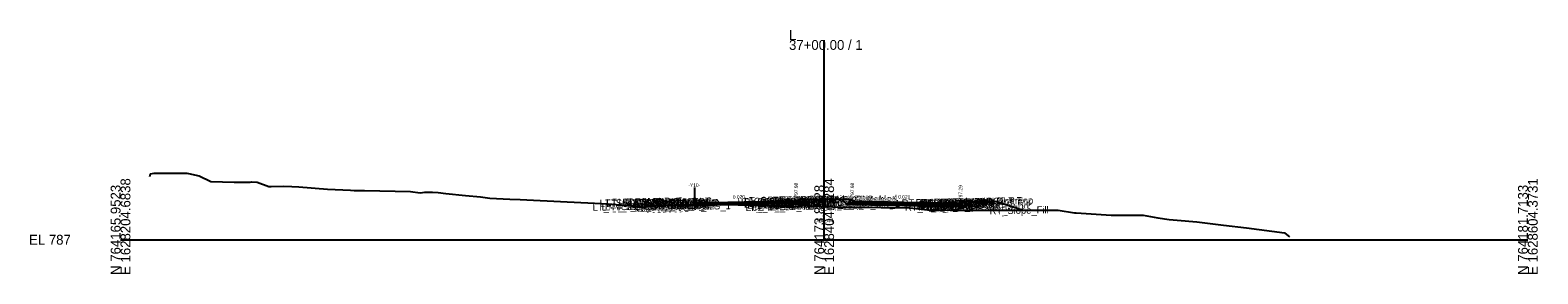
# Model space of a CAD drawing. Extents: x -26 to 4403, y -510 to 9556.
# Drawn here: x 1974.3 to 2402.8, y 6990.3 to 7059.6 of the extents above; entities that cross this region are included whole.
import ezdxf

# ---------------------------------------------------------------- set-up
doc = ezdxf.new("R2010")
doc.units = 0
for name, color, linetype in [('Default', 7, 'Continuous'), ('Exist CMT Pavement', 7, 'Continuous'), ('Exist Cross Section Cell', 7, 'Continuous'), ('Exist XS Center Line Elevation Label', 7, 'Continuous'), ('Exist XS Ground Line', 7, 'Continuous'), ('Prop CMT Conc Surface', 7, 'Continuous'), ('Prop CMT Concrete Structures', 7, 'Continuous'), ('Prop CMT Pvmt Course 1', 7, 'Continuous'), ('Prop CMT Pvmt Course 1 CG', 7, 'Continuous'), ('Prop CMT Pvmt Course 2', 7, 'Continuous'), ('Prop CMT Pvmt Course 2 Wedge', 7, 'Continuous'), ('Prop CMT Pvmt Course 3', 7, 'Continuous'), ('Prop CMT Pvmt Course 3 Wedge', 7, 'Continuous'), ('Prop CMT Pvmt Surface', 7, 'Continuous'), ('Prop CMT Shear Line', 7, 'Continuous'), ('Prop CMT Slope Grass', 7, 'Continuous'), ('Prop CMT Subgrade Earthwork', 7, 'Continuous'), ('Prop XS Hydro Elevations', 7, 'Continuous'), ('Prop XS SE Text', 7, 'Continuous'), ('Prop XS Side Slope Text', 7, 'Continuous'), ('Scratch_Level_0', 7, 'Continuous')]:
    doc.layers.add(name, color=color, linetype=linetype)

msp = doc.modelspace()

# ---------------------------------------------------------------- linework, layer by layer
at = {"layer": 'Exist CMT Pavement'}
for points in [[(2149.21, 7009.52), (2149.21, 7009.52)], [(2163.25, 7009.95), (2169.01, 7009.97), (2172.14, 7009.98), (2178.99, 7009.83), (2181.8, 7009.77), (2184.46, 7009.67), (2191.07, 7009.43)]]:
    msp.add_lwpolyline(points, dxfattribs=at)
at = {"layer": 'Exist Cross Section Cell'}
for p, q in [((2200, 7000), (2200, 7056.77)), ((2000, 7000), (2200, 7000)), ((2200, 7000), (2400, 7000))]:
    msp.add_line(p, q, dxfattribs=at)
at = {"layer": 'Exist XS Ground Line'}
msp.add_lwpolyline([(2008.31, 7017.94), (2008.54, 7018.7), (2009.52, 7018.92), (2018.01, 7018.92), (2018.86, 7018.91), (2019.34, 7018.83), (2022.31, 7018.12), (2025.65, 7016.51), (2032.34, 7016.34), (2036.84, 7016.37), (2037.31, 7016.49), (2038.86, 7016.36), (2042.15, 7015.14), (2042.83, 7015.17), (2046.28, 7015.22), (2048.72, 7015.1), (2050.63, 7015.02), (2058.81, 7014.34), (2065.32, 7014.05), (2066.36, 7013.97), (2069.31, 7013.99), (2082.42, 7013.68), (2085.13, 7013.38), (2086.47, 7013.57), (2088.62, 7013.52), (2090.31, 7013.45), (2092.41, 7013.18), (2098.08, 7012.57), (2102.31, 7012.2), (2105, 7011.85), (2110.65, 7011.58), (2113.57, 7011.47), (2126.99, 7010.79), (2136.72, 7010.27), (2142.3, 7009.89), (2143.35, 7009.87), (2145.26, 7009.77), (2146.89, 7009.54), (2148.79, 7009.29), (2149.21, 7009.52), (2157.72, 7009.8), (2161.95, 7009.94), (2169.01, 7009.97), (2172.14, 7009.98), (2178.99, 7009.83), (2181.8, 7009.77), (2184.46, 7009.67), (2191.07, 7009.43), (2192.27, 7009.33), (2194.26, 7009.69), (2195.18, 7009.65), (2196.21, 7009.57), (2196.73, 7009.55), (2200, 7009.44), (2204.69, 7009.28), (2207.03, 7009.29), (2207.93, 7009.28), (2224.4, 7009.09), (2227.6, 7008.72), (2229.34, 7008.47), (2235.8, 7008.39), (2239.47, 7008.39), (2240.18, 7008.39), (2240.57, 7008.39), (2262.9, 7008.39), (2266.5, 7008.37), (2271.16, 7007.61), (2271.57, 7007.61), (2281.58, 7006.96), (2282.47, 7006.94), (2284.59, 7006.94), (2290.67, 7007), (2294.83, 7006.27), (2298.06, 7005.77), (2300.35, 7005.52), (2305.96, 7005.12), (2313.49, 7004.12), (2320.03, 7003.38), (2330.8, 7001.94), (2331.89, 7001.14), (2332.29, 7000.82)], dxfattribs=at)
at = {"layer": 'Prop CMT Conc Surface'}
for points in [[(2191.25, 7010.97), (2192, 7010.98), (2192, 7011.15), (2192.76, 7011.4)], [(2208.75, 7010.97), (2208, 7010.98), (2208, 7011.15), (2207.24, 7011.4)], [(2243.25, 7010.88), (2248.25, 7010.98)], [(2236.75, 7010.41), (2238.75, 7010.29)], [(2238.75, 7010.29), (2238.75, 7010.79), (2239.25, 7010.79)]]:
    msp.add_lwpolyline(points, dxfattribs=at)
at = {"layer": 'Prop CMT Concrete Structures'}
for points in [[(2191.25, 7010.97), (2192, 7010.98), (2192, 7011.15), (2192.76, 7011.4)], [(2191.25, 7010.39), (2191.25, 7010.97)], [(2192.76, 7011.4), (2192.76, 7010.42)], [(2208.75, 7010.97), (2208, 7010.98), (2208, 7011.15), (2207.24, 7011.4)], [(2207.24, 7011.4), (2207.24, 7010.42)], [(2208.75, 7010.39), (2208.75, 7010.97)], [(2248.25, 7010.98), (2243.25, 7010.88)], [(2243.25, 7010.88), (2243.25, 7010.55)], [(2248.25, 7010.65), (2248.25, 7010.98)], [(2192.76, 7010.42), (2191.25, 7010.39)], [(2207.24, 7010.42), (2208.75, 7010.39)], [(2236.75, 7010.41), (2238.75, 7010.29), (2238.75, 7010.79), (2239.25, 7010.79)], [(2239.25, 7010.79), (2239.25, 7009.78), (2236.75, 7009.83)], [(2236.75, 7009.83), (2236.75, 7010.41)], [(2243.25, 7010.55), (2248.25, 7010.65)]]:
    msp.add_lwpolyline(points, dxfattribs=at)
at = {"layer": 'Prop CMT Pvmt Course 1'}
for points in [[(2191.25, 7010.97), (2163.25, 7010.41)], [(2191.25, 7010.72), (2191.25, 7010.97)], [(2208.75, 7010.97), (2236.75, 7010.41)], [(2208.75, 7010.72), (2208.75, 7010.97)], [(2163.25, 7010.16), (2191.07, 7010.72), (2191.25, 7010.72)], [(2236.75, 7010.16), (2208.75, 7010.72)], [(2208.75, 7010.72), (2208.75, 7010.72), (2208.75, 7010.72)], [(2236.75, 7010.41), (2236.75, 7010.16)]]:
    msp.add_lwpolyline(points, dxfattribs=at)
at = {"layer": 'Prop CMT Pvmt Course 1 CG'}
for points in [[(2191.25, 7010.39), (2193.26, 7010.43), (2193.59, 7010.1)], [(2191.25, 7010.05), (2191.25, 7010.39)], [(2193.59, 7010.1), (2191.25, 7010.05)], [(2208.75, 7010.39), (2206.74, 7010.43), (2206.41, 7010.1)], [(2206.41, 7010.1), (2208.75, 7010.05)], [(2208.75, 7010.05), (2208.75, 7010.39)], [(2236.75, 7009.83), (2239.75, 7009.77), (2240.09, 7009.43)], [(2236.75, 7009.49), (2236.75, 7009.83)], [(2240.09, 7009.43), (2236.75, 7009.49)]]:
    msp.add_lwpolyline(points, dxfattribs=at)
at = {"layer": 'Prop CMT Pvmt Course 2'}
for points in [[(2191.07, 7010.72), (2191.07, 7010.38)], [(2191.25, 7010.72), (2191.07, 7010.72)], [(2191.07, 7010.38), (2191.25, 7010.39)], [(2191.25, 7010.39), (2191.25, 7010.72)], [(2208.75, 7010.39), (2208.75, 7010.72)], [(2208.75, 7010.72), (2236.75, 7010.16)], [(2236.75, 7009.83), (2208.75, 7010.39)], [(2236.75, 7010.16), (2236.75, 7009.83)]]:
    msp.add_lwpolyline(points, dxfattribs=at)
at = {"layer": 'Prop CMT Pvmt Course 2 Wedge'}
for points in [[(2191.07, 7010.38), (2191.07, 7010.38), (2184.46, 7010.25), (2181.8, 7010.2), (2178.99, 7010.14), (2172.14, 7010), (2170.63, 7009.97), (2169.01, 7009.97), (2161.95, 7009.94), (2160.34, 7009.89)], [(2163.25, 7010.16), (2169.01, 7010.27), (2172.14, 7010.34), (2178.99, 7010.47), (2181.8, 7010.53), (2184.46, 7010.58), (2191.07, 7010.72), (2191.07, 7010.72)], [(2191.07, 7010.72), (2191.07, 7010.38)]]:
    msp.add_lwpolyline(points, dxfattribs=at)
at = {"layer": 'Prop CMT Pvmt Course 3'}
for points in [[(2191.25, 7010.39), (2191.07, 7010.38)], [(2191.07, 7010.38), (2191.07, 7010.05)], [(2191.07, 7010.05), (2191.25, 7010.05)], [(2191.25, 7010.05), (2191.25, 7010.39)], [(2208.75, 7010.39), (2236.75, 7009.83)], [(2208.75, 7010.05), (2208.75, 7010.39)], [(2236.75, 7009.49), (2208.75, 7010.05)], [(2236.75, 7009.83), (2236.75, 7009.49)]]:
    msp.add_lwpolyline(points, dxfattribs=at)
at = {"layer": 'Prop CMT Pvmt Course 3 Wedge'}
for points in [[(2170.63, 7009.97), (2172.14, 7010)], [(2191.07, 7009.43), (2191.07, 7009.43), (2184.46, 7009.67), (2181.8, 7009.77), (2178.99, 7009.83), (2172.14, 7009.98), (2170.63, 7009.97)], [(2172.14, 7010), (2178.99, 7010.14), (2181.8, 7010.2), (2184.46, 7010.25), (2191.07, 7010.38), (2191.07, 7010.38)], [(2191.07, 7010.38), (2191.07, 7009.43)]]:
    msp.add_lwpolyline(points, dxfattribs=at)
at = {"layer": 'Prop CMT Pvmt Surface'}
for points in [[(2191.25, 7010.97), (2163.25, 7010.41)], [(2208.75, 7010.97), (2236.75, 7010.41)]]:
    msp.add_lwpolyline(points, dxfattribs=at)
at = {"layer": 'Prop CMT Shear Line'}
msp.add_line((2163.25, 7008.58), (2163.25, 7014.84), dxfattribs=at)
at = {"layer": 'Prop CMT Slope Grass'}
for points in [[(2192.76, 7011.4), (2200, 7011.55)], [(2207.24, 7011.4), (2200, 7011.55)], [(2239.25, 7010.79), (2248.75, 7010.98), (2256.53, 7008.39)]]:
    msp.add_lwpolyline(points, dxfattribs=at)
at = {"layer": 'Prop CMT Subgrade Earthwork'}
for points in [[(2194.93, 7011.44), (2193.59, 7010.1)], [(2205.07, 7011.44), (2206.41, 7010.1)], [(2236.75, 7009.49), (2240.09, 7009.43), (2241.5, 7010.83)], [(2191.25, 7010.05), (2191.07, 7010.05)], [(2191.07, 7010.05), (2191.07, 7009.43)], [(2193.59, 7010.1), (2191.25, 7010.05)], [(2191.25, 7010.05), (2191.25, 7010.05)], [(2206.41, 7010.1), (2208.75, 7010.05)], [(2208.75, 7010.05), (2236.75, 7009.49)], [(2208.75, 7010.05), (2208.75, 7010.05)], [(2208.75, 7010.05), (2208.75, 7010.05)], [(2236.75, 7009.49), (2236.75, 7009.49)]]:
    msp.add_lwpolyline(points, dxfattribs=at)

# ---------------------------------------------------------------- texts
at = {"layer": 'Default'}
msp.add_text('-', height=0.0001, dxfattribs=at).set_placement((2000, 7000))
at = {"layer": 'Exist Cross Section Cell'}
for s, p in [('L', (2190, 7056.77)), ('37+00.00 / 1', (2190, 7053.97)), ('EL 787', (1974, 6998.6))]:
    msp.add_text(s, height=2.8, dxfattribs=at).set_placement(p)
for s, p in [('N 764165.9523', (2000, 6990)), ('E 1628204.6838', (2002.8, 6990)), ('N 764173.8328', (2200, 6990)), ('E 1628404.5284', (2202.8, 6990)), ('N 764181.7133', (2400, 6990)), ('E 1628604.3731', (2402.8, 6990))]:
    msp.add_text(s, height=2.8, rotation=90, dxfattribs=at).set_placement(p)
at = {"layer": 'Exist XS Center Line Elevation Label'}
msp.add_text('796.44', height=1.2, dxfattribs=at).set_placement((2197.53, 7004.84))
at = {"layer": 'Prop XS Hydro Elevations'}
for s, rotation, p in [('-Y10-', 360, (2161.39, 7015)), ('797.98', 90, (2192.5, 7011.98)), ('797.98', 90, (2208.5, 7011.98)), ('797.29', 90, (2239.25, 7011.29))]:
    msp.add_text(s, height=1, rotation=rotation, dxfattribs=at).set_placement(p)
at = {"layer": 'Prop XS SE Text'}
for rotation, p in [(1.1456, (2174.03, 7011.62)), (358.8542, (2221.02, 7011.72))]:
    msp.add_text('0.020', height=1, rotation=rotation, dxfattribs=at).set_placement(p)
at = {"layer": 'Prop XS Side Slope Text'}
msp.add_text('3:1', height=1, rotation=341.5695, dxfattribs=at).set_placement((2252.12, 7010.65))
at = {"layer": 'Scratch_Level_0'}
for s, p in [('LT_Sub_Trench_Out_DLT', (2136.19, 7009.39)), ('LT_SDWK_Out_Top', (2138.01, 7009.59)), ('LT_SDWK_Out_Bot', (2138.04, 7009.26)), ('LT_CSLP_Pnt', (2141.44, 7009.67)), ('LT_CG1_Shelf_Out', (2143.92, 7008.44)), ('LT_SDWK_In_Top', (2144.63, 7009.52)), ('LT_SDWK_In_Bot', (2144.66, 7009.19)), ('LT_CG_Top_Face', (2145.63, 7009.48)), ('LT_CG_Top_BOC', (2146.15, 7009.5)), ('LT_CG_Bot_BOC', (2146.18, 7008.48)), ('LT_CG_Top_Gut', (2146.6, 7009)), ('LT_PV2_OEEOP', (2149.67, 7008.89)), ('LT_PV3_OEEOP', (2149.67, 7008.55)), ('LT_CG_Bot_IE', (2150.28, 7008.57)), ('LT_PV2_OEOT', (2150.54, 7008.9)), ('LT_PV3_OEOT', (2150.54, 7008.57)), ('LT_PV1_OEOT', (2151.11, 7009.17)), ('37+00.00', (2151.22, 7009.59)), ('LT_CG_Top_Face_Med', (2175.39, 7009.82)), ('LT_CG_Top_Gut_Med', (2176.37, 7009.67)), ('LT_CG_Top_BOC_Med', (2177.18, 7010.09)), ('LT_CG_Bot_BOC_Med', (2177.21, 7009.1)), ('LT_CG_Bot_IE_Med', (2177.34, 7009.11)), ('LT_Sub_IEOT_CG_1', (2178.14, 7008.79)), ('LT_Sub_IEEOP', (2180.95, 7008.85)), ('LT_PV2_IEEOP', (2181.04, 7009.52)), ('LT_PV3_IEEOP', (2181.04, 7009.18)), ('LT_CG1_Shelf_In', (2181.46, 7009.19)), ('LT_Sub_PGL', (2182.39, 7008.88)), ('LT_PV2_PGL', (2182.48, 7009.54)), ('LT_PV3_PGL', (2182.48, 7009.21)), ('LT_PV1_PGL', (2183.05, 7009.8)), ('LT_Sub_DLT_In', (2183.9, 7010.22)), ('LT_Sub_IEOP', (2184.36, 7008.92)), ('37+00.00', (2184.47, 7009.83)), ('MD_Crown Point', (2187.09, 7010.29)), ('37+00.00', (2187.76, 7010.3)), ('37+00.00', (2189.66, 7010.34)), ('RT_CG_Top_Face_Med', (2191.34, 7009.82)), ('RT_CG_Top_BOC_Med', (2191.61, 7010.09)), ('RT_CG_Bot_BOC_Med', (2191.64, 7009.1)), ('RT_CG_Top_Gut_Med', (2192.32, 7009.67)), ('RT_Sub_DLT_In', (2193.99, 7010.22)), ('RT_CG_Bot_IE_Med', (2194.79, 7009.11)), ('RT_CG1_Shelf_In', (2194.89, 7009.19)), ('RT_Sub_IEOT_CG_1', (2195.59, 7008.79)), ('RT_Sub_IEOP', (2197.14, 7008.91)), ('RT_Sub_OEEOP', (2197.94, 7008.84)), ('RT_PV2_OEEOP', (2198.03, 7009.5)), ('RT_PV3_OEEOP', (2198.03, 7009.17)), ('RT_Sub_IEEOP', (2198.58, 7008.85)), ('RT_PV2_IEEOP', (2198.68, 7009.52)), ('RT_Sub_PGL', (2199.84, 7008.87)), ('RT_PV2_PGL', (2199.94, 7009.54)), ('37+00.00', (2200.11, 7010.27)), ('RT_PV1_PGL', (2200.5, 7009.8)), ('37+00.00', (2201.01, 7010.07)), ('37+00.00', (2201.19, 7009.91)), ('37+00.00', (2201.21, 7009.85)), ('RT_Sub_Trench_Out_DLT', (2222.04, 7009.44)), ('RT_CG_Top_Face', (2225.99, 7009.53)), ('RT_CG1_Shelf_Out', (2226.28, 7008.5)), ('RT_CG_Bot_IE', (2226.64, 7008.62)), ('RT_PV2_OEOT', (2226.9, 7008.96)), ('RT_PV3_OEOT', (2226.9, 7008.63)), ('RT_CG_Top_Gut', (2226.96, 7009.05)), ('RT_PV1_OEOT', (2227.46, 7009.22)), ('RT_CG_Top_BOC', (2227.51, 7009.55)), ('RT_CG_Bot_BOC', (2227.54, 7008.54)), ('RT_SDWK_In_Top', (2231.08, 7009.64)), ('RT_SDWK_In_Bot', (2231.12, 7009.3)), ('37+00.00', (2232.16, 7009.65)), ('37+00.00', (2234.5, 7009.69)), ('RT_SDWK_Out_Top', (2234.46, 7009.7)), ('RT_SDWK_Out_Bot', (2234.49, 7009.37)), ('RT_CSLP_Pnt', (2238.9, 7009.78)), ('LT_PV_Sub_Tie_Out', (2134.18, 7008.22)), ('LT_PV_OEEOP_EG', (2136.77, 7008.27)), ('LT_Slope_Fill', (2137.71, 7008.31)), ('LT_Sub_OEOT_CG_1', (2146.59, 7008.16)), ('LT_Sub_OEOP', (2147.14, 7008.17)), ('LT_Sub_OEEOP', (2149.58, 7008.22)), ('LT_Sub_OEOT', (2150.45, 7008.24)), ('LT_PV_Sub_Tie_In', (2177.66, 7008.16)), ('LT_PV_IEEOP_EG', (2179.28, 7008.2)), ('RT_Sub_OEOT_CG_1', (2222.95, 7008.22)), ('RT_Sub_OEOT', (2226.8, 7008.29)), ('RT_Sub_OEOP', (2230.17, 7008.23)), ('37+00.00', (2246.9, 7008.19)), ('RT_Slope_Fill', (2247.02, 7007.2))]:
    msp.add_text(s, height=2, rotation=1.1458, dxfattribs=at).set_placement(p)

doc.saveas('drawing.dxf')
